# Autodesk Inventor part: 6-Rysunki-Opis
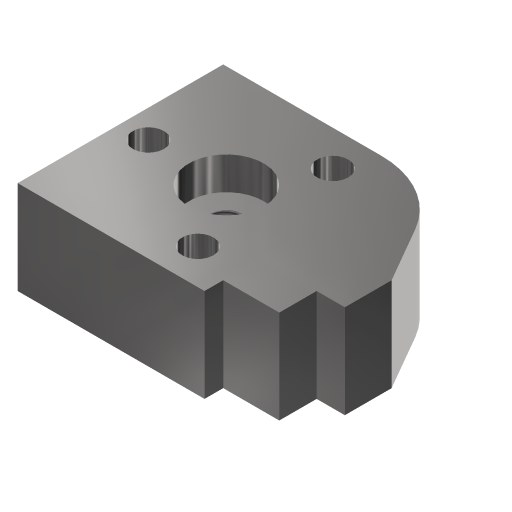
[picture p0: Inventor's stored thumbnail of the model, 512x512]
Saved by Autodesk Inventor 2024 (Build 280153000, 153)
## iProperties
Company: ATC
Created: 2023-03
Part Number: 6-Rysunki-Opis
Material: 18G2A-Rez.
Document SubType Name: Modeling
Designer: Andrzej Jaskulski
Manufacturer: Standard
Standards Organization: Custom
Density: 1 g/cm^3
Appearance: Stal — polerowana
Checked By: A.J.
Engr Approved By: Andrzej Jaskulski
Mfg Approved By: Andrzej Jaskulski
Authority: A.J.
Moduł_X: 3,000 mm
Title: A.J.: Kurs R2024-MEP
Author: Andrzej Jaskulski
Revision Number: 1/24
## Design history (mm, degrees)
sketch "Szkic1"
  geometry: L1 (0, 0)-(60, 0); L2 (60, 0)-(60, 6); L3 (60, 6)-(78, 6); L4 (78, 6)-(78, 18); L5 (78, 18)-(87.053, 18); L6 (87.053, 18)-(87.053, 33); L7 (87.053, 33)-(68, 66); L8 (68, 66)-(0, 66); L9 (0, 66)-(0, 0)
  constraints: 18 end point, 6 parallel, 1 horizontal, 1 perpendicular, 1 other
  dimensions: "d0" = 60 distance of L1.start L1.end (= 20 x Moduł_X); "d1" = 18 distance of L2.end L3.end (= 6 x Moduł_X); "d2" = 9.05256 distance of L4.end L5.end (derived); "d3" = 66 distance of L8.end L1.start (= 22 x Moduł_X); "d4" = 150 deg angle of L7 L6; "d5" = 6 distance of L1.end L2.end (= 2 x Moduł_X); "d6" = 12 distance of L3.end L4.end (= 4 x Moduł_X); "d7" = 15 distance of L5.end L6.end (= 5 x Moduł_X); "d19" = 68 distance of L7.end L8.end
extrude "BAZA" new body sketch "Szkic1" distance "d8" = 30 (= 10 x Moduł_X); taper "d9" = 0 deg
hole "Otwór M12" diameter "d12" = 10.106; stored, may be unused: countersink angle "d16" = 90 deg, drill point angle "d18" = 118 deg; dims "d10" = 34 (= 0.5 x d19), "d11" = 33 (= 0.5 x d3), "d13" = 24 (= 8 x Moduł_X), "d14" = 24, "d15" = 10.5, "d17" = 8
node "Oś otw. M12"
node "Pł. Symetrii"
sketch "Szkic2"
  geometry: L1 (104.463, 33)-(-17.411, 33) reference; 2 further points
  constraints: 1 point on line
  dimensions: "d21" = 25 distance of point (34, 33) point (9, 33) (computed from d19)
hole "Otwór Fi10" sketch "Szkic2" diameter "d22" = 10; stored, may be unused: countersink angle "d26" = 90 deg, drill point angle "d28" = 118 deg; dims "d23" = 6, "d24" = 3.6, "d25" = 5.3, "d27" = 8
node "Oś Oryginału"
pattern_circular "Szyk kołowy 1" dims angle "d31" = 360 deg
fillet "Zaokrąglenie1" dims "d32" = 30
node "Bryła1"
node "Korpusy bryłowe"
node "Korpusy powierzchniowe"
other parameters: "Moduł_X" = 3 [user parameter; used in 8 equation terms], "d20" = 0
